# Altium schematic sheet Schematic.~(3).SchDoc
size A4; SheetNumber: 1; SheetTotal: 1
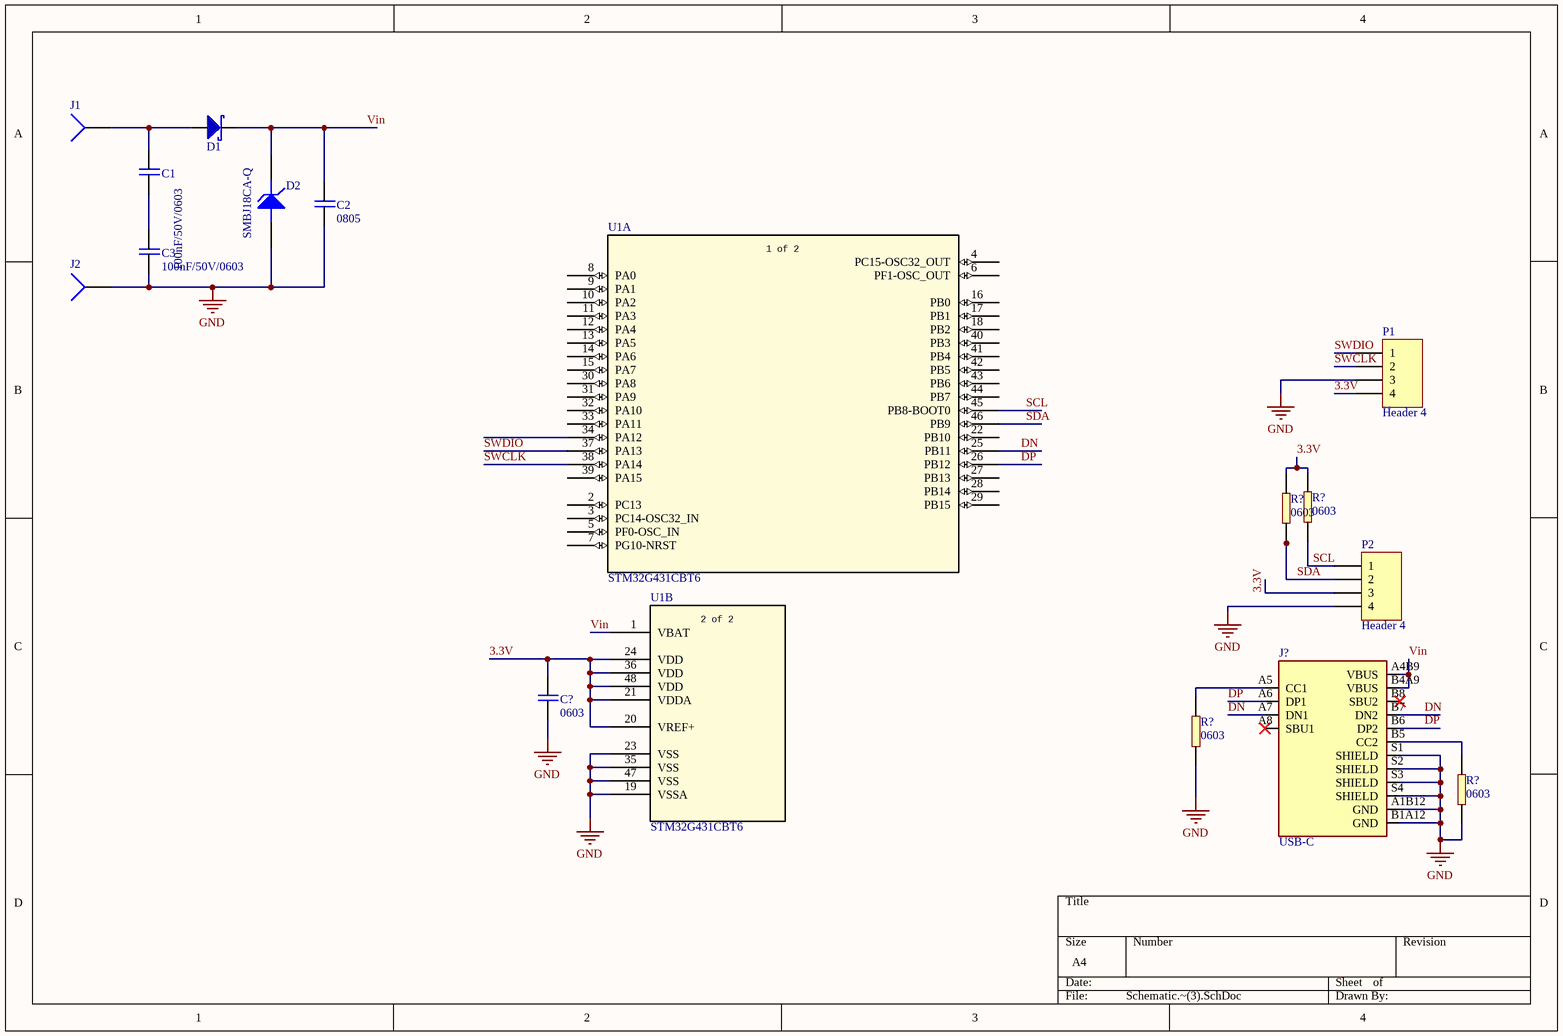
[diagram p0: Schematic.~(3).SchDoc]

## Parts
(Parts that share a designator on the sheet are numbered #1, #2 ... from top to bottom, then left to right.)
C1  100nF/50V/0603  [C0603]
C2  0805  [C0805]
C3  100nF/50V/0603  [C0603]
C?  0603  [C0603]
D1  RB058LAM-60TF  (value not drawn)
D2  SMBJ18CA-Q  [SMBJ18CA-Q]
J1  Socket  [PIN1]  (value not drawn)
J2  Socket  [PIN1]  (value not drawn)
J?  USB-C  [HRO_TYPE-C-31-M-12]
P1  Header 4  [HDR1X4]
P2  Header 4  [HDR1X4]
R?#1  0603  [R0603]
R?#2  0603  [R0603]
R?#3  0603  [R0603]
R?#4  0603  [R0603]
U1  STM32G431CBT6  [LQFP48-7x7mm]  (parts A,B of 2)

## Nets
GND: C2.1 C3.1 C?.1 D2.A J2.1 J?.A1B12(GND) J?.B1A12(GND) J?.S1(SHIELD) J?.S2(SHIELD) J?.S3(SHIELD) J?.S4(SHIELD) P1.3 P2.4 R?#3.1 R?#4.1 U1.19(VSSA) U1.23(VSS) U1.35(VSS) U1.47(VSS)
3.3V: C?.2 P1.4 P2.3 R?#1.2 R?#2.2 U1.20(VREF+) U1.21(VDDA) U1.24(VDD) U1.36(VDD) U1.48(VDD)
DN: J?.A7(DN1) J?.B7(DN2) U1.25(PB11)
DP: J?.A6(DP1) J?.B6(DP2) U1.26(PB12)
SCL: P2.1 R?#2.1 U1.45(PB8-BOOT0)
SDA: P2.2 R?#1.1 U1.46(PB9)
SWCLK: P1.2 U1.38(PA14)
SWDIO: P1.1 U1.37(PA13)
Vin: C2.2 D1.K D2.K J?.A4B9(VBUS) J?.B4A9(VBUS) U1.1(VBAT)
NetC1_1: C1.1 C3.2
NetC1_2: C1.2 D1.A J1.1
NetJ?_A5: J?.A5(CC1) R?#3.2
NetJ?_B5: J?.B5(CC2) R?#4.2

Not connected (* = marked no-connect by the designer): J? A8(SBU1)* B8(SBU2)*; U1 2(PC13) 3(PC14-OSC32_IN) 4(PC15-OSC32_OUT) 5(PF0-OSC_IN) 6(PF1-OSC_OUT) 7(PG10-NRST) 8(PA0) 9(PA1) 10(PA2) 11(PA3) 12(PA4) 13(PA5) 14(PA6) 15(PA7) 16(PB0) 17(PB1) 18(PB2) 22(PB10) 27(PB13) 28(PB14) 29(PB15) 30(PA8) 31(PA9) 32(PA10) 33(PA11) 34(PA12) 39(PA15) 40(PB3) 41(PB4) 42(PB5) 43(PB6) 44(PB7)

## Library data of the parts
C1 C3 C? = C0603
C2 = C0805
D1 = RB058LAM-60TF: Schottky Barrier Diode 60V 3A SOD-128
J? = USB-C: USB-C (USB TYPE-C) USB 3.2 Gen 2 (USB 3.1 Gen 2, Superspeed + (USB 3.1)) Receptacle Connector 24 Position Surface Mount, Through Hole; MF: Adam Technologies
P1 P2 = Header 4: Header, 4-Pin
R?#1-R?#4 = R0603
U1 = STM32G431CBT6: Mainstream Arm Cortex-M4 MCU 170 MHz with 128 Kbytes of Flash memory, Math Accelerator, Medium Analog level integration; Manufacturer_Name: STMicroelectronics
